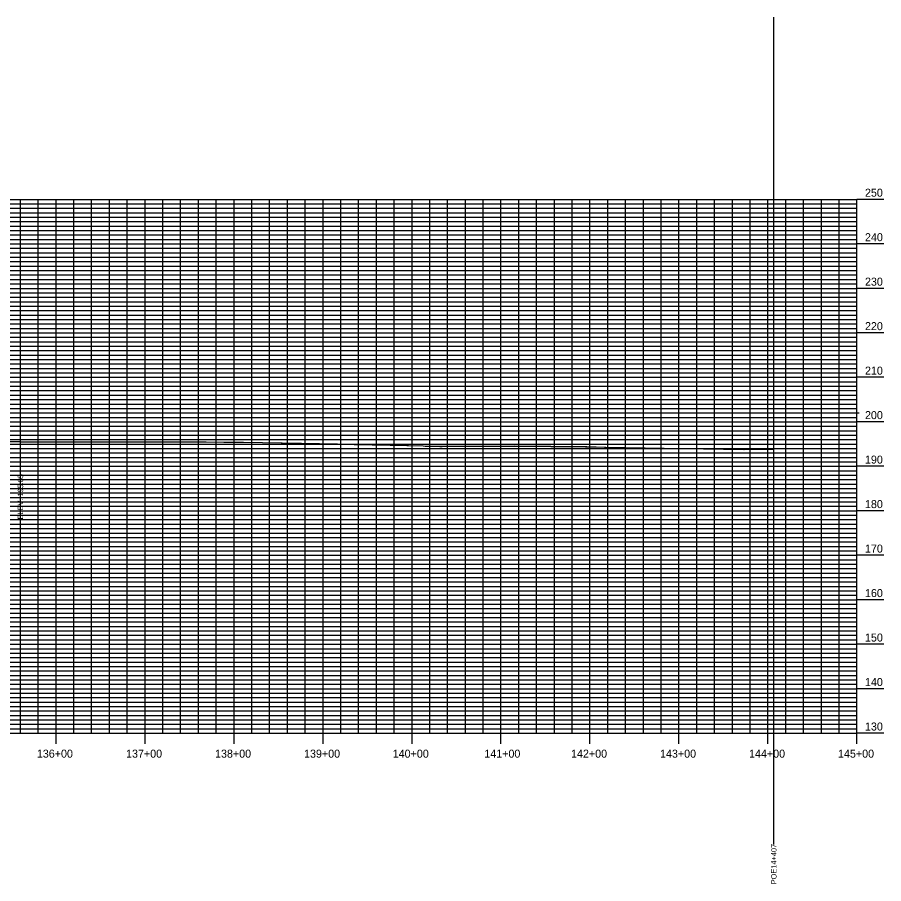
# Model space of a CAD drawing. Extents: x 1451449 to 1456010, y 297581 to 299758.
# Drawn here: x 1455036 to 1456010, y 298784 to 299758 of the extents above; entities that cross this region are included whole.
import ezdxf

# ---------------------------------------------------------------- set-up
doc = ezdxf.new("R2010")
doc.units = 0
for name, color, linetype in [('Existing Profile Grade', 7, 'Continuous'), ('Grid', 7, 'Continuous'), ('Grid_Labels', 7, 'Continuous'), ('Grid_Major', 7, 'Continuous'), ('Grid_Minor', 7, 'Continuous'), ('PCPT', 7, 'Continuous'), ('PR_Exist Surface', 7, 'Continuous'), ('PRF_Scratch', 7, 'Continuous'), ('Profile Annotation', 7, 'Continuous'), ('Proposed Tangents', 7, 'Continuous')]:
    doc.layers.add(name, color=color, linetype=linetype)

msp = doc.modelspace()

# ---------------------------------------------------------------- linework, layer by layer
at = {"layer": 'Existing Profile Grade'}
msp.add_lwpolyline([(1455018.68, 299281.58), (1455040.15, 299281.23), (1455061.62, 299280.89), (1455081.77, 299280.99), (1455101.92, 299281.1), (1455123.66, 299281.09), (1455145.39, 299281.08), (1455167.13, 299281.08), (1455188.86, 299281.07), (1455208.68, 299281), (1455228.49, 299280.93), (1455248.3, 299280.85), (1455268.12, 299280.78), (1455289.97, 299280.52), (1455311.83, 299280.25), (1455333.68, 299279.99), (1455355.54, 299279.72), (1455375.81, 299279.23), (1455396.09, 299278.73), (1455416.36, 299278.24), (1455436.64, 299277.75), (1455455.22, 299277.33), (1455473.81, 299276.91), (1455492.39, 299276.49), (1455510.98, 299276.07), (1455532.02, 299276.15), (1455553.06, 299276.23), (1455574.11, 299276.31), (1455595.15, 299276.39), (1455615.4, 299276.2), (1455635.64, 299276.01), (1455655.89, 299275.82), (1455676.14, 299275.63), (1455697.54, 299275.18), (1455718.93, 299274.72), (1455740.32, 299274.27), (1455761.72, 299273.81), (1455784.49, 299273.5), (1455807.27, 299273.19), (1455830.04, 299272.88), (1455852.82, 299272.57), (1455874.94, 299272.84), (1455886.23, 299272.98)], dxfattribs=at)
at = {"layer": 'Grid'}
for p, q in [((1455979.67, 298953.55), (1455979.67, 299553.55)), ((1456009.67, 299553.55), (1455979.67, 299553.55)), ((1456009.67, 299553.55), (1455979.67, 299553.55)), ((1456009.67, 299503.55), (1455979.67, 299503.55)), ((1456009.67, 299453.55), (1455979.67, 299453.55)), ((1456009.67, 299403.55), (1455979.67, 299403.55)), ((1456009.67, 299353.55), (1455979.67, 299353.55)), ((1456009.67, 299303.55), (1455979.67, 299303.55)), ((1456009.67, 299253.55), (1455979.67, 299253.55)), ((1456009.67, 299203.55), (1455979.67, 299203.55)), ((1456009.67, 299153.55), (1455979.67, 299153.55)), ((1456009.67, 299103.55), (1455979.67, 299103.55)), ((1456009.67, 299053.55), (1455979.67, 299053.55)), ((1456009.67, 299003.55), (1455979.67, 299003.55)), ((1451479.67, 298953.55), (1455979.67, 298953.55)), ((1455079.67, 298941.55), (1455079.67, 298953.55)), ((1455179.67, 298941.55), (1455179.67, 298953.55)), ((1455279.67, 298941.55), (1455279.67, 298953.55)), ((1455379.67, 298941.55), (1455379.67, 298953.55)), ((1455479.67, 298941.55), (1455479.67, 298953.55)), ((1455579.67, 298941.55), (1455579.67, 298953.55)), ((1455679.67, 298941.55), (1455679.67, 298953.55)), ((1455779.67, 298941.55), (1455779.67, 298953.55)), ((1455879.67, 298941.55), (1455879.67, 298953.55)), ((1456009.67, 298953.55), (1455979.67, 298953.55)), ((1455979.67, 298941.55), (1455979.67, 298953.55))]:
    msp.add_line(p, q, dxfattribs=at)
at = {"layer": 'Grid_Major'}
for p, q in [((1451479.67, 299553.55), (1455979.67, 299553.55)), ((1451479.67, 299553.55), (1455979.67, 299553.55)), ((1455079.67, 298953.55), (1455079.67, 299553.55)), ((1455179.67, 298953.55), (1455179.67, 299553.55)), ((1455279.67, 298953.55), (1455279.67, 299553.55)), ((1455379.67, 298953.55), (1455379.67, 299553.55)), ((1455479.67, 298953.55), (1455479.67, 299553.55)), ((1455579.67, 298953.55), (1455579.67, 299553.55)), ((1455679.67, 298953.55), (1455679.67, 299553.55)), ((1455779.67, 298953.55), (1455779.67, 299553.55)), ((1455879.67, 298953.55), (1455879.67, 299553.55)), ((1451479.67, 299503.55), (1455979.67, 299503.55)), ((1451479.67, 299453.55), (1455979.67, 299453.55)), ((1451479.67, 299403.55), (1455979.67, 299403.55)), ((1451479.67, 299353.55), (1455979.67, 299353.55)), ((1451479.67, 299303.55), (1455979.67, 299303.55)), ((1451479.67, 299253.55), (1455979.67, 299253.55)), ((1451479.67, 299203.55), (1455979.67, 299203.55)), ((1451479.67, 299153.55), (1455979.67, 299153.55)), ((1451479.67, 299103.55), (1455979.67, 299103.55)), ((1451479.67, 299053.55), (1455979.67, 299053.55)), ((1451479.67, 299003.55), (1455979.67, 299003.55))]:
    msp.add_line(p, q, dxfattribs=at)
at = {"layer": 'Grid_Minor'}
for p, q in [((1451479.67, 299548.55), (1455979.67, 299548.55)), ((1455039.67, 298953.55), (1455039.67, 299553.55)), ((1455059.67, 298953.55), (1455059.67, 299553.55)), ((1455099.67, 298953.55), (1455099.67, 299553.55)), ((1455119.67, 298953.55), (1455119.67, 299553.55)), ((1455139.67, 298953.55), (1455139.67, 299553.55)), ((1455159.67, 298953.55), (1455159.67, 299553.55)), ((1455199.67, 298953.55), (1455199.67, 299553.55)), ((1455219.67, 298953.55), (1455219.67, 299553.55)), ((1455239.67, 298953.55), (1455239.67, 299553.55)), ((1455259.67, 298953.55), (1455259.67, 299553.55)), ((1455299.67, 298953.55), (1455299.67, 299553.55)), ((1455319.67, 298953.55), (1455319.67, 299553.55)), ((1455339.67, 298953.55), (1455339.67, 299553.55)), ((1455359.67, 298953.55), (1455359.67, 299553.55)), ((1455399.67, 298953.55), (1455399.67, 299553.55)), ((1455419.67, 298953.55), (1455419.67, 299553.55)), ((1455439.67, 298953.55), (1455439.67, 299553.55)), ((1455459.67, 298953.55), (1455459.67, 299553.55)), ((1455499.67, 298953.55), (1455499.67, 299553.55)), ((1455519.67, 298953.55), (1455519.67, 299553.55)), ((1455539.67, 298953.55), (1455539.67, 299553.55)), ((1455559.67, 298953.55), (1455559.67, 299553.55)), ((1455599.67, 298953.55), (1455599.67, 299553.55)), ((1455619.67, 298953.55), (1455619.67, 299553.55)), ((1455639.67, 298953.55), (1455639.67, 299553.55)), ((1455659.67, 298953.55), (1455659.67, 299553.55)), ((1455699.67, 298953.55), (1455699.67, 299553.55)), ((1455719.67, 298953.55), (1455719.67, 299553.55)), ((1455739.67, 298953.55), (1455739.67, 299553.55)), ((1455759.67, 298953.55), (1455759.67, 299553.55)), ((1455799.67, 298953.55), (1455799.67, 299553.55)), ((1455819.67, 298953.55), (1455819.67, 299553.55)), ((1455839.67, 298953.55), (1455839.67, 299553.55)), ((1455859.67, 298953.55), (1455859.67, 299553.55)), ((1455899.67, 298953.55), (1455899.67, 299553.55)), ((1455919.67, 298953.55), (1455919.67, 299553.55)), ((1455939.67, 298953.55), (1455939.67, 299553.55)), ((1455959.67, 298953.55), (1455959.67, 299553.55)), ((1451479.67, 299543.55), (1455979.67, 299543.55)), ((1451479.67, 299538.55), (1455979.67, 299538.55)), ((1451479.67, 299533.55), (1455979.67, 299533.55)), ((1451479.67, 299528.55), (1455979.67, 299528.55)), ((1451479.67, 299523.55), (1455979.67, 299523.55)), ((1451479.67, 299518.55), (1455979.67, 299518.55)), ((1451479.67, 299513.55), (1455979.67, 299513.55)), ((1451479.67, 299508.55), (1455979.67, 299508.55)), ((1451479.67, 299498.55), (1455979.67, 299498.55)), ((1451479.67, 299493.55), (1455979.67, 299493.55)), ((1451479.67, 299488.55), (1455979.67, 299488.55)), ((1451479.67, 299483.55), (1455979.67, 299483.55)), ((1451479.67, 299478.55), (1455979.67, 299478.55)), ((1451479.67, 299473.55), (1455979.67, 299473.55)), ((1451479.67, 299468.55), (1455979.67, 299468.55)), ((1451479.67, 299463.55), (1455979.67, 299463.55)), ((1451479.67, 299458.55), (1455979.67, 299458.55)), ((1451479.67, 299448.55), (1455979.67, 299448.55)), ((1451479.67, 299443.55), (1455979.67, 299443.55)), ((1451479.67, 299438.55), (1455979.67, 299438.55)), ((1451479.67, 299433.55), (1455979.67, 299433.55)), ((1451479.67, 299428.55), (1455979.67, 299428.55)), ((1451479.67, 299423.55), (1455979.67, 299423.55)), ((1451479.67, 299418.55), (1455979.67, 299418.55)), ((1451479.67, 299413.55), (1455979.67, 299413.55)), ((1451479.67, 299408.55), (1455979.67, 299408.55)), ((1451479.67, 299398.55), (1455979.67, 299398.55)), ((1451479.67, 299393.55), (1455979.67, 299393.55)), ((1451479.67, 299388.55), (1455979.67, 299388.55)), ((1451479.67, 299383.55), (1455979.67, 299383.55)), ((1451479.67, 299378.55), (1455979.67, 299378.55)), ((1451479.67, 299373.55), (1455979.67, 299373.55)), ((1451479.67, 299368.55), (1455979.67, 299368.55)), ((1451479.67, 299363.55), (1455979.67, 299363.55)), ((1451479.67, 299358.55), (1455979.67, 299358.55)), ((1451479.67, 299348.55), (1455979.67, 299348.55)), ((1451479.67, 299343.55), (1455979.67, 299343.55)), ((1451479.67, 299338.55), (1455979.67, 299338.55)), ((1451479.67, 299333.55), (1455979.67, 299333.55)), ((1451479.67, 299328.55), (1455979.67, 299328.55)), ((1451479.67, 299323.55), (1455979.67, 299323.55)), ((1451479.67, 299318.55), (1455979.67, 299318.55)), ((1451482.2, 299313.64), (1455982.2, 299313.64)), ((1451479.67, 299308.55), (1455979.67, 299308.55)), ((1451479.67, 299298.55), (1455979.67, 299298.55)), ((1451479.67, 299293.55), (1455979.67, 299293.55)), ((1451479.67, 299288.55), (1455979.67, 299288.55)), ((1451479.67, 299283.55), (1455979.67, 299283.55)), ((1451479.67, 299278.55), (1455979.67, 299278.55)), ((1451479.67, 299273.55), (1455979.67, 299273.55)), ((1451479.67, 299268.55), (1455979.67, 299268.55)), ((1451479.67, 299263.55), (1455979.67, 299263.55)), ((1451479.67, 299258.55), (1455979.67, 299258.55)), ((1451479.67, 299248.55), (1455979.67, 299248.55)), ((1451479.67, 299243.55), (1455979.67, 299243.55)), ((1451479.67, 299238.55), (1455979.67, 299238.55)), ((1451479.67, 299233.55), (1455979.67, 299233.55)), ((1451479.67, 299228.55), (1455979.67, 299228.55)), ((1451479.67, 299223.55), (1455979.67, 299223.55)), ((1451479.67, 299218.55), (1455979.67, 299218.55)), ((1451479.67, 299213.55), (1455979.67, 299213.55)), ((1451479.67, 299208.55), (1455979.67, 299208.55)), ((1451479.67, 299198.55), (1455979.67, 299198.55)), ((1451479.67, 299193.55), (1455979.67, 299193.55)), ((1451479.67, 299188.55), (1455979.67, 299188.55)), ((1451479.67, 299183.55), (1455979.67, 299183.55)), ((1451479.67, 299178.55), (1455979.67, 299178.55)), ((1451479.67, 299173.55), (1455979.67, 299173.55)), ((1451479.67, 299168.55), (1455979.67, 299168.55)), ((1451479.67, 299163.55), (1455979.67, 299163.55)), ((1451479.67, 299158.55), (1455979.67, 299158.55)), ((1451479.67, 299148.55), (1455979.67, 299148.55)), ((1451479.67, 299143.55), (1455979.67, 299143.55)), ((1451479.67, 299138.55), (1455979.67, 299138.55)), ((1451479.67, 299133.55), (1455979.67, 299133.55)), ((1451479.67, 299128.55), (1455979.67, 299128.55)), ((1451479.67, 299123.55), (1455979.67, 299123.55)), ((1451479.67, 299118.55), (1455979.67, 299118.55)), ((1451479.67, 299113.55), (1455979.67, 299113.55)), ((1451479.67, 299108.55), (1455979.67, 299108.55)), ((1451479.67, 299098.55), (1455979.67, 299098.55)), ((1451479.67, 299093.55), (1455979.67, 299093.55)), ((1451479.67, 299088.55), (1455979.67, 299088.55)), ((1451479.67, 299083.55), (1455979.67, 299083.55)), ((1451479.67, 299078.55), (1455979.67, 299078.55)), ((1451479.67, 299073.55), (1455979.67, 299073.55)), ((1451479.67, 299068.55), (1455979.67, 299068.55)), ((1451479.67, 299063.55), (1455979.67, 299063.55)), ((1451479.67, 299058.55), (1455979.67, 299058.55)), ((1451479.67, 299048.55), (1455979.67, 299048.55)), ((1451479.67, 299043.55), (1455979.67, 299043.55)), ((1451479.67, 299038.55), (1455979.67, 299038.55)), ((1451479.67, 299033.55), (1455979.67, 299033.55)), ((1451479.67, 299028.55), (1455979.67, 299028.55)), ((1451479.67, 299023.55), (1455979.67, 299023.55)), ((1451479.67, 299018.55), (1455979.67, 299018.55)), ((1451479.67, 299013.55), (1455979.67, 299013.55)), ((1451479.67, 299008.55), (1455979.67, 299008.55)), ((1451479.67, 298998.55), (1455979.67, 298998.55)), ((1451479.67, 298993.55), (1455979.67, 298993.55)), ((1451479.67, 298988.55), (1455979.67, 298988.55)), ((1451479.67, 298983.55), (1455979.67, 298983.55)), ((1451479.67, 298978.55), (1455979.67, 298978.55)), ((1451479.67, 298973.55), (1455979.67, 298973.55)), ((1451479.67, 298968.55), (1455979.67, 298968.55)), ((1451479.67, 298963.55), (1455979.67, 298963.55)), ((1451479.67, 298958.55), (1455979.67, 298958.55))]:
    msp.add_line(p, q, dxfattribs=at)
at = {"layer": 'PR_Exist Surface'}
msp.add_lwpolyline([(1455018.68, 299281.55), (1455039.66, 299281.21), (1455040.16, 299281.2), (1455061.07, 299280.86), (1455061.64, 299280.85), (1455081.13, 299280.94), (1455081.78, 299280.95), (1455101.14, 299281.04), (1455101.93, 299281.04), (1455122.86, 299281.04), (1455123.67, 299281.05), (1455144.66, 299281.05), (1455145.41, 299281.05), (1455166.46, 299281.05), (1455167.15, 299281.06), (1455188.26, 299281.05), (1455188.88, 299281.06), (1455208.34, 299280.99), (1455208.69, 299280.99), (1455228.37, 299280.92), (1455228.49, 299280.92), (1455238.84, 299280.89), (1455248.3, 299280.85), (1455248.41, 299280.85), (1455268.11, 299280.77), (1455268.48, 299280.76), (1455289.97, 299280.5), (1455290.51, 299280.49), (1455311.83, 299280.23), (1455332.82, 299279.97), (1455333.69, 299279.95), (1455354.52, 299279.69), (1455355.56, 299279.68), (1455374.67, 299279.2), (1455375.83, 299279.17), (1455394.74, 299278.7), (1455396.1, 299278.67), (1455414.81, 299278.2), (1455416.37, 299278.16), (1455434.89, 299277.7), (1455436.64, 299277.65), (1455438.25, 299277.61), (1455455.19, 299277.22), (1455456.96, 299277.18), (1455473.74, 299276.79), (1455475.67, 299276.74), (1455492.28, 299276.36), (1455494.37, 299276.3), (1455510.82, 299275.92), (1455513.42, 299275.93), (1455531.89, 299276.01), (1455534.36, 299276.02), (1455552.97, 299276.1), (1455555.3, 299276.11), (1455574.04, 299276.19), (1455576.23, 299276.2), (1455595.11, 299276.28), (1455597.08, 299276.27), (1455615.37, 299276.11), (1455617.25, 299276.1), (1455635.63, 299275.93), (1455637.41, 299275.92), (1455655.89, 299275.75), (1455674.56, 299275.58), (1455676.15, 299275.58), (1455695.94, 299275.16), (1455697.54, 299275.12), (1455717.41, 299274.7), (1455718.93, 299274.67), (1455738.89, 299274.25), (1455740.32, 299274.22), (1455741.73, 299274.19), (1455761.71, 299273.76), (1455763.14, 299273.75), (1455784.49, 299273.47), (1455785.6, 299273.46), (1455807.27, 299273.17), (1455829.58, 299272.88), (1455830.04, 299272.87), (1455852.69, 299272.57), (1455852.82, 299272.57), (1455852.94, 299272.57), (1455874.94, 299272.84), (1455874.98, 299272.84), (1455885.27, 299272.97), (1455886.23, 299272.98)], dxfattribs=at)
at = {"layer": 'Proposed Tangents'}
msp.add_line((1455886.23, 298828.55), (1455886.23, 299758.16), dxfattribs=at)

# ---------------------------------------------------------------- texts
at = {"layer": 'Grid_Labels'}
for s, p in [('250', (1455988.67, 299556.55)), ('250', (1455988.67, 299556.55)), ('240', (1455988.67, 299506.55)), ('230', (1455988.67, 299456.55)), ('220', (1455988.67, 299406.55)), ('210', (1455988.67, 299356.55)), ('200', (1455988.67, 299306.55)), ('190', (1455988.67, 299256.55)), ('180', (1455988.67, 299206.55)), ('170', (1455988.67, 299156.55)), ('160', (1455988.67, 299106.55)), ('150', (1455988.67, 299056.55)), ('140', (1455988.67, 299006.55)), ('130', (1455988.67, 298956.55)), ('136+00', (1455058.16, 298926.05)), ('137+00', (1455158.37, 298926.05)), ('138+00', (1455258.37, 298926.05)), ('139+00', (1455358.37, 298926.05)), ('140+00', (1455458.02, 298926.05)), ('141+00', (1455560.92, 298926.05)), ('142+00', (1455658.37, 298926.05)), ('143+00', (1455758.37, 298926.05)), ('144+00', (1455858.37, 298926.05)), ('145+00', (1455958.37, 298926.05))]:
    msp.add_text(s, height=9, dxfattribs=at).set_placement(p)
at = {"layer": 'PCPT'}
msp.add_text('POE14+407', height=6, rotation=90, dxfattribs=at).set_placement((1455889.23, 298783.76))
at = {"layer": 'PRF_Scratch'}
msp.add_text('ELEV. 195.85', height=6, rotation=90, dxfattribs=at).set_placement((1455042.74, 299193.79))
at = {"layer": 'Profile Annotation'}
msp.add_text('ELEV. 195.85', height=6, rotation=90, dxfattribs=at).set_placement((1455042.74, 299193.79))

doc.saveas('drawing.dxf')
